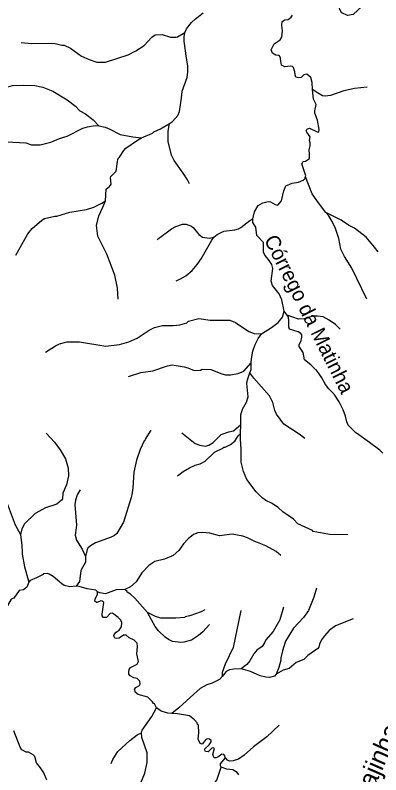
# Model space of a CAD drawing. Extents: x 393 to 446.6, y 8175.5 to 8231.
# Drawn here: x 426.13 to 430.1, y 8184.16 to 8192.41 of the extents above; entities that cross this region are included whole.
import ezdxf
from ezdxf.enums import TextEntityAlignment as Align

# ---------------------------------------------------------------- set-up
doc = ezdxf.new("R2010")
doc.units = 0
doc.header["$LTSCALE"] = 0.064
doc.linetypes.add('LONG_DASHED', pattern=[7.5, 6, -1.5])
doc.layers.add('61', color=7, linetype='Continuous')
doc.layers.add('7', color=7, linetype='Continuous', lineweight=25)
doc.layers.add('9', color=7, linetype='LONG_DASHED', lineweight=25)

msp = doc.modelspace()

# ---------------------------------------------------------------- linework, layer by layer
at = {"layer": '7'}
for points in [[(426.4711, 8187.8712), (426.5598, 8187.7758), (426.6212, 8187.6918), (426.6793, 8187.5949), (426.71, 8187.4916), (426.7132, 8187.4076), (426.689, 8187.3107), (426.6518, 8187.2203), (426.6454, 8187.1573), (426.6373, 8187.146), (426.584, 8187.1008), (426.463, 8187.0604), (426.3515, 8186.999), (426.2336, 8186.8876), (426.2062, 8186.8327), (426.191, 8186.7726)], [(427.6051, 8187.9065), (427.5448, 8187.8081), (427.5416, 8187.7919), (427.5351, 8187.7903), (427.5125, 8187.7435), (427.4899, 8187.695), (427.4496, 8187.5788), (427.4205, 8187.4496), (427.4108, 8187.2784), (427.4011, 8187.2041), (427.3917, 8187.1728), (427.3107, 8186.9038), (427.2364, 8186.7827), (427.2106, 8186.7617), (427.1735, 8186.7423), (427.0055, 8186.6825), (426.9506, 8186.6486), (426.9232, 8186.6228), (426.9134, 8186.6067), (426.8983, 8186.5331)], [(425.9034, 8187.7173), (425.93, 8187.6854), (425.9817, 8187.5982), (426.0092, 8187.5077), (426.0124, 8187.4431), (426.0027, 8187.3721), (426.0027, 8187.2946), (426.0237, 8187.1654), (426.1351, 8186.8747), (426.191, 8186.7726)], [(426.8403, 8187.2571), (426.8069, 8187.2009), (426.7875, 8187.1428), (426.7811, 8187.0976), (426.7988, 8186.8715), (426.7954, 8186.8431), (426.7859, 8186.7649), (426.8004, 8186.7084), (426.8618, 8186.6115), (426.8983, 8186.5331)], [(429.0152, 8186.5434), (429.0151, 8186.5435), (428.9643, 8186.5873), (428.8545, 8186.6486), (428.7269, 8186.6971), (428.6558, 8186.7358), (428.6058, 8186.7536), (428.4879, 8186.7746), (428.3523, 8186.7568), (428.2457, 8186.7859), (428.1649, 8186.7923), (428.1165, 8186.7891), (428.0681, 8186.7713), (428.0099, 8186.7245), (427.9598, 8186.6696), (427.9082, 8186.5986), (427.8484, 8186.5436), (427.7548, 8186.5049), (427.6482, 8186.4791), (427.5836, 8186.4355), (427.5077, 8186.3548), (427.4479, 8186.2579), (427.3834, 8186.2013), (427.3237, 8186.1725)], [(426.191, 8186.7726), (426.2062, 8186.6519), (426.2087, 8186.5789), (426.2094, 8186.5582), (426.2352, 8186.4194), (426.2831, 8186.2549)], [(426.8983, 8186.5331), (426.8957, 8186.471), (426.8456, 8186.3806), (426.8311, 8186.2595), (426.797, 8186.2103)], [(426.797, 8186.2103), (426.7278, 8186.2013), (426.6664, 8186.2175), (426.6389, 8186.2336), (426.5453, 8186.3143), (426.5033, 8186.3418), (426.4823, 8186.3467), (426.4419, 8186.3434), (426.4355, 8186.3353), (426.3661, 8186.2998), (426.296, 8186.27), (426.2831, 8186.2549)], [(426.2831, 8186.2549), (426.2595, 8186.1997), (426.2255, 8186.1706), (426.1755, 8186.1626), (426.1206, 8186.0786), (426.0916, 8186.0673), (426.0512, 8186.0011), (425.9992, 8185.9862)], [(427.0267, 8186.1485), (427.0081, 8186.1659), (426.9151, 8186.182), (426.8279, 8186.2062), (426.797, 8186.2103)], [(427.6663, 8184.8892), (427.6454, 8184.9299), (427.6337, 8184.9354), (427.624, 8184.9547), (427.5739, 8185.0048), (427.4674, 8185.0339), (427.4383, 8185.0532), (427.4302, 8185.092), (427.4415, 8185.1097), (427.4835, 8185.1323), (427.4883, 8185.1469), (427.4851, 8185.176), (427.456, 8185.2066), (427.4221, 8185.2131), (427.3801, 8185.2341), (427.3672, 8185.2535), (427.3672, 8185.2793), (427.3721, 8185.3051), (427.385, 8185.3261), (427.456, 8185.3616), (427.4706, 8185.3923), (427.4544, 8185.4763), (427.4625, 8185.5538), (427.4577, 8185.5893), (427.4253, 8185.6248), (427.372, 8185.6474), (427.3397, 8185.6782), (427.3075, 8185.6781), (427.2607, 8185.6442), (427.2348, 8185.641), (427.2203, 8185.6442), (427.2106, 8185.6539), (427.2025, 8185.6733), (427.209, 8185.683), (427.2283, 8185.7104), (427.2607, 8185.7314), (427.2865, 8185.7669), (427.2897, 8185.8154), (427.2784, 8185.8396), (427.251, 8185.8687), (427.1912, 8185.9155), (427.1654, 8185.9139), (427.1234, 8185.8687), (427.0879, 8185.8703), (427.078, 8185.8859), (427.0763, 8185.9071), (427.0959, 8186.0318), (427.0766, 8186.0479), (427.062, 8186.0496), (427.0249, 8186.0334), (427.0152, 8186.0334), (426.9991, 8186.0463), (427.0023, 8186.0673), (427.0279, 8186.1217), (427.0267, 8186.1485)], [(427.3237, 8186.1725), (427.2284, 8186.169), (427.1153, 8186.127), (427.0507, 8186.1367), (427.0267, 8186.1485)], [(427.57, 8185.9221), (427.4334, 8186.0802), (427.3833, 8186.1238), (427.3478, 8186.1464), (427.3478, 8186.1529), (427.3237, 8186.1725)], [(429.4042, 8186.1887), (429.376, 8186.0899), (429.3163, 8185.9446), (429.263, 8185.8687), (429.1548, 8185.7541), (429.0676, 8185.612), (429.0353, 8185.5086), (429.0159, 8185.4311), (429.0159, 8185.4053), (428.9933, 8185.3245), (428.9667, 8185.2523)], [(429.0458, 8185.9809), (429.0046, 8185.8445), (428.9336, 8185.7185), (428.8528, 8185.6281), (428.8399, 8185.5926), (428.8124, 8185.5554), (428.7576, 8185.5134), (428.7236, 8185.4731), (428.68, 8185.3972), (428.6477, 8185.36), (428.587, 8185.3104)], [(428.1917, 8185.9529), (428.152, 8185.9301), (428.0293, 8185.8864), (427.9776, 8185.8752), (427.9744, 8185.8703), (427.8775, 8185.8606), (427.7128, 8185.8622), (427.6547, 8185.8816), (427.57, 8185.9221)], [(428.2414, 8185.7918), (428.1698, 8185.7137), (428.123, 8185.6733), (428.0487, 8185.6232), (427.9647, 8185.6006), (427.9324, 8185.5974), (427.8404, 8185.6087), (427.7967, 8185.6291), (427.7618, 8185.6558), (427.6902, 8185.725), (427.653, 8185.7734), (427.5745, 8185.9169), (427.57, 8185.9221)], [(428.5836, 8185.9454), (428.4992, 8185.5441), (428.412, 8185.3633), (428.3797, 8185.2729), (428.3795, 8185.2348), (428.3795, 8185.2301)], [(429.8033, 8185.8544), (429.6118, 8185.7782), (429.5408, 8185.7266), (429.4891, 8185.6701), (429.4584, 8185.6265), (429.4374, 8185.5796), (429.4309, 8185.5473), (429.4196, 8185.5344), (429.3115, 8185.4569), (429.2662, 8185.4133), (429.1823, 8185.381), (429.108, 8185.3164), (429.0434, 8185.2987), (428.9667, 8185.2523)], [(428.587, 8185.3104), (428.5073, 8185.3099), (428.4588, 8185.3003), (428.4233, 8185.2825), (428.3795, 8185.2301)], [(428.9667, 8185.2523), (428.9465, 8185.2325), (428.8948, 8185.2163), (428.8544, 8185.2195), (428.7915, 8185.2373), (428.6881, 8185.2841), (428.587, 8185.3104)], [(428.3795, 8185.2301), (428.3504, 8185.1953), (428.2699, 8185.1566), (428.2134, 8185.1388), (428.1423, 8185.0968), (428.0309, 8185.0015), (427.9114, 8184.8885), (427.8343, 8184.8269)], [(427.506, 8184.6176), (427.5118, 8184.6467), (427.6175, 8184.7949), (427.6663, 8184.8892)], [(427.8343, 8184.8269), (427.7887, 8184.8304), (427.7193, 8184.8514), (427.6663, 8184.8892)], [(428.4115, 8184.348), (428.4107, 8184.3654), (428.3991, 8184.3814), (428.3765, 8184.3831), (428.3345, 8184.3524), (428.3136, 8184.3433), (428.2925, 8184.3459), (428.2844, 8184.3605), (428.2805, 8184.3804), (428.2957, 8184.4444), (428.283, 8184.4521), (428.2683, 8184.4493), (428.2279, 8184.4105), (428.2005, 8184.4122), (428.1915, 8184.4264), (428.1908, 8184.4428), (428.2392, 8184.4848), (428.2618, 8184.5204), (428.2602, 8184.5316), (428.244, 8184.5478), (428.2214, 8184.5526), (428.2037, 8184.5445), (428.1617, 8184.4945), (428.1423, 8184.4994), (428.1197, 8184.5462), (428.1262, 8184.6172), (428.123, 8184.7012), (428.1133, 8184.7076), (428.1084, 8184.7238), (428.081, 8184.7593), (428.026, 8184.8029), (427.8937, 8184.8223), (427.8343, 8184.8269)], [(426.4774, 8184.1037), (426.4451, 8184.1813), (426.4096, 8184.2362), (426.3644, 8184.2894), (426.3466, 8184.3588), (426.3289, 8184.3766), (426.2789, 8184.4057), (426.253, 8184.4073), (426.2046, 8184.4299), (426.1868, 8184.459), (426.119, 8184.6366)], [(428.9991, 8184.6987), (428.8641, 8184.572), (428.7204, 8184.4638), (428.6203, 8184.375), (428.5557, 8184.3314), (428.4976, 8184.312), (428.4604, 8184.3088), (428.4378, 8184.3185), (428.4123, 8184.3471), (428.4115, 8184.348)], [(427.177, 8184.2827), (427.1928, 8184.3265), (427.2461, 8184.4138), (427.3769, 8184.5348), (427.4577, 8184.5946), (427.506, 8184.6176)], [(427.4826, 8184.0466), (427.5145, 8184.1177), (427.5416, 8184.178), (427.5642, 8184.2943), (427.5642, 8184.3976), (427.5093, 8184.5656), (427.506, 8184.6176)], [(428.3699, 8184.2432), (428.3617, 8184.2584), (428.3617, 8184.2805), (428.4118, 8184.341), (428.4115, 8184.348)], [(427.8211, 8183.7769), (427.829, 8183.8292), (427.8452, 8183.8648), (427.8597, 8183.8857), (427.9033, 8183.9148), (427.9198, 8183.923), (427.926, 8183.9261), (428.0455, 8183.9455), (428.1391, 8183.9745), (428.1585, 8183.9858), (428.215, 8183.9987), (428.2473, 8184.0246), (428.2554, 8184.0246), (428.3216, 8184.1021), (428.3699, 8184.2432)], [(428.5594, 8184.1583), (428.542, 8184.1851), (428.496, 8184.2135), (428.4298, 8184.2232), (428.3699, 8184.2432)]]:
    msp.add_lwpolyline(points, dxfattribs=at)
at = {"layer": '9'}
for p, q in [((429.0857, 8189.1526), (429.0536, 8189.1987)), ((428.5793, 8187.8689), (428.5812, 8187.9667))]:
    msp.add_line(p, q, dxfattribs=at)
for points in [[(429.9468, 8192.5417), (429.9012, 8192.5125), (429.8023, 8192.4215), (429.7394, 8192.4102), (429.6796, 8192.4393), (429.6667, 8192.4538), (429.6554, 8192.4781), (429.6198, 8192.6234), (429.5778, 8192.6848), (429.5229, 8192.7493), (429.347, 8192.8591), (429.2947, 8192.9408), (429.2714, 8192.956), (429.2025, 8192.9747), (429.1581, 8192.9968)], [(427.9736, 8192.2271), (427.9911, 8192.2668), (428.0487, 8192.3343), (428.089, 8192.3747), (428.173, 8192.4409)], [(429.3621, 8191.6072), (429.3554, 8191.6833), (429.3426, 8191.737), (429.2985, 8191.774), (429.2678, 8191.7659), (429.2383, 8191.7373), (429.2091, 8191.7327), (429.1811, 8191.7408), (429.1706, 8191.7642), (429.1693, 8191.7982), (429.1532, 8191.8467), (429.1421, 8191.8566), (429.1176, 8191.8601), (429.0604, 8191.8543), (429.0224, 8191.8709), (429.0176, 8191.9145), (429.0145, 8191.9431), (429.0099, 8191.9613), (428.9998, 8191.9742), (428.9627, 8191.979), (428.9255, 8192.0017), (428.9126, 8192.0372), (428.9432, 8192.1034), (429.0078, 8192.147), (429.0288, 8192.1761), (429.0353, 8192.2423), (429.0272, 8192.3004), (429.0323, 8192.346), (429.0591, 8192.3624), (429.0953, 8192.367), (429.1303, 8192.3927), (429.1431, 8192.4137)], [(426.1999, 8192.1166), (426.3114, 8192.1055), (426.5275, 8192.1099), (426.5679, 8192.1067), (426.6406, 8192.0873), (426.6664, 8192.0873), (426.7326, 8192.055), (426.8537, 8191.9678), (426.9361, 8191.9306), (427.0184, 8191.9048), (427.1121, 8191.9015), (427.3608, 8191.9823), (427.4448, 8192.0259), (427.5335, 8192.0841), (427.6175, 8192.1745), (427.6546, 8192.2019), (427.729, 8192.2051), (427.821, 8192.1761), (427.8807, 8192.1761), (427.8969, 8192.1793), (427.9736, 8192.2271)], [(427.8094, 8191.2371), (427.8425, 8191.2603), (427.8985, 8191.3245), (427.9166, 8191.3671), (427.9404, 8191.5124), (427.9469, 8191.5899), (427.9986, 8191.7353), (428.0067, 8191.7998), (428.0083, 8191.8644), (427.9921, 8191.9452), (427.9679, 8192.1325), (427.9663, 8192.1777), (427.9736, 8192.2271)], [(425.8437, 8191.5644), (425.9495, 8191.606), (426.1045, 8191.648), (426.2272, 8191.6545), (426.3467, 8191.6513), (426.4339, 8191.6303), (426.5421, 8191.5867), (426.6971, 8191.4946), (426.7875, 8191.4252), (426.836, 8191.3751), (426.8957, 8191.3412), (426.9813, 8191.2767), (427.0426, 8191.2114)], [(429.284, 8190.6609), (429.2863, 8190.6693), (429.2452, 8190.8003), (429.2581, 8190.8229), (429.2582, 8190.8229), (429.2856, 8190.8293), (429.3292, 8190.8584), (429.3263, 8190.9027), (429.3241, 8190.95), (429.3352, 8190.9929), (429.3333, 8191.0281), (429.3263, 8191.0526), (429.3362, 8191.0905), (429.3001, 8191.1426), (429.292, 8191.1569), (429.2936, 8191.1684), (429.3047, 8191.1781), (429.3292, 8191.1846), (429.4099, 8191.1458), (429.4245, 8191.1442), (429.4309, 8191.1458), (429.4341, 8191.1733), (429.4164, 8191.2734), (429.3873, 8191.3509), (429.3841, 8191.3751), (429.4018, 8191.4446), (429.3712, 8191.5027), (429.3621, 8191.6072)], [(429.9543, 8191.6306), (429.8169, 8191.6174), (429.701, 8191.5913), (429.5569, 8191.5398), (429.4988, 8191.5334), (429.4681, 8191.5383), (429.4132, 8191.5689), (429.3621, 8191.6072)], [(427.503, 8191.0809), (427.6256, 8191.133), (427.6401, 8191.1458), (427.7112, 8191.1781), (427.8075, 8191.2358), (427.8094, 8191.2371)], [(428.0244, 8190.581), (428.0046, 8190.6242), (427.9582, 8190.6969), (427.8581, 8190.8342), (427.8306, 8190.8923), (427.7951, 8191.0409), (427.7951, 8191.1539), (427.8094, 8191.2371)], [(425.6977, 8190.9926), (425.8219, 8191.0183), (426.0383, 8191.0377), (426.2482, 8191.028), (426.3112, 8191.0037), (426.4048, 8191.0037), (426.5211, 8191.0328), (426.6131, 8191.0732), (426.6987, 8191.1006), (426.8667, 8191.1846), (426.9183, 8191.2007), (427.0023, 8191.2136), (427.0426, 8191.2114)], [(427.0426, 8191.2114), (427.1092, 8191.1963), (427.1621, 8191.1765), (427.2736, 8191.1167), (427.4092, 8191.0909), (427.503, 8191.0809)], [(427.1123, 8190.3981), (427.1217, 8190.5217), (427.1557, 8190.5516), (427.1751, 8190.5774), (427.167, 8190.6469), (427.1734, 8190.6614), (427.23, 8190.7195), (427.2428, 8190.8253), (427.2461, 8190.8455), (427.2558, 8190.8649), (427.2655, 8190.8697), (427.3128, 8190.9449), (427.3349, 8190.9682), (427.4593, 8191.0554), (427.503, 8191.0809)], [(428.714, 8190.1996), (428.7301, 8190.2787), (428.7721, 8190.3449), (428.8206, 8190.3756), (428.8787, 8190.3885), (428.9029, 8190.3853), (428.9562, 8190.3562), (428.9853, 8190.3481), (429.0224, 8190.3966), (429.0482, 8190.5048), (429.0708, 8190.5613), (429.1387, 8190.5871), (429.2097, 8190.5984), (429.2581, 8190.6194), (429.2775, 8190.6372), (429.284, 8190.6609)], [(429.5065, 8190.2712), (429.4244, 8190.3764), (429.3582, 8190.4741), (429.285, 8190.6584), (429.284, 8190.6609)], [(426.1394, 8189.805), (426.2724, 8190.0365), (426.3192, 8190.0962), (426.421, 8190.1882), (426.4533, 8190.206), (426.5631, 8190.2318), (426.5873, 8190.2318), (426.7278, 8190.2738), (426.9086, 8190.3013), (426.9877, 8190.3272), (427.0733, 8190.3707), (427.1123, 8190.3981)], [(427.2504, 8189.3271), (427.2445, 8189.4471), (427.2154, 8189.5892), (427.1299, 8189.8185), (427.0297, 8190.0139), (427.0168, 8190.1269), (427.041, 8190.2335), (427.0862, 8190.3272), (427.1123, 8190.3981)], [(429.9494, 8189.3272), (429.7862, 8189.6651), (429.707, 8189.791), (429.6683, 8189.8702), (429.6473, 8189.988), (429.6085, 8190.0946), (429.573, 8190.1705), (429.5359, 8190.2335), (429.5065, 8190.2712)], [(430.072, 8189.8415), (430.0349, 8189.8944), (429.9412, 8190.001), (429.8169, 8190.1011), (429.7523, 8190.1334), (429.6731, 8190.185), (429.5065, 8190.2712)], [(428.2905, 8190.0011), (428.3267, 8190.0326), (428.3991, 8190.0656), (428.517, 8190.08), (428.5557, 8190.093), (428.5832, 8190.1075), (428.6793, 8190.1831), (428.714, 8190.1996)], [(429.0536, 8189.1987), (429.0289, 8189.32), (428.9998, 8189.3857), (428.9271, 8189.4778), (428.911, 8189.5246), (428.9303, 8189.6602), (428.9174, 8189.7054), (428.8835, 8189.7587), (428.8415, 8189.8055), (428.8302, 8189.8395), (428.8302, 8189.9428), (428.7576, 8190.0187), (428.7462, 8190.1108), (428.7139, 8190.1624), (428.714, 8190.1996)], [(427.6748, 8189.9778), (427.8307, 8190.093), (427.8759, 8190.1172), (427.9486, 8190.1447), (427.9906, 8190.1447), (428.0455, 8190.1204), (428.0648, 8190.1059), (428.1262, 8190.0316), (428.1681, 8190.0009), (428.2441, 8189.9928), (428.2905, 8190.0011)], [(427.8798, 8189.5278), (427.9292, 8189.5488), (427.9841, 8189.5827), (428.0535, 8189.6409), (428.11, 8189.7054), (428.152, 8189.7668), (428.2666, 8189.9702), (428.2905, 8190.0011)], [(428.8071, 8188.9512), (428.9144, 8189.02), (428.9869, 8189.0757), (429.0353, 8189.1338), (429.0536, 8189.1987)], [(426.4621, 8188.7522), (426.5711, 8188.8221), (426.6163, 8188.8415), (426.6987, 8188.8641), (426.8311, 8188.8641), (427.1169, 8188.8189), (427.2671, 8188.8367), (427.3688, 8188.8657), (427.456, 8188.9045), (427.5868, 8188.9917), (427.6466, 8189.0208), (427.7322, 8189.0434), (427.8468, 8189.0418), (427.9211, 8189.0482), (427.997, 8189.0724), (428.0164, 8189.0886), (428.1262, 8189.1176), (428.2489, 8189.0983), (428.462, 8189.1015), (428.5234, 8189.074), (428.6704, 8188.9756), (428.7285, 8188.9562), (428.8071, 8188.9512)], [(429.6611, 8189.0008), (429.6086, 8189.0531), (429.5408, 8189.1015), (429.4745, 8189.137), (429.4148, 8189.1451), (429.376, 8189.1435), (429.3227, 8189.1322), (429.2695, 8189.1128), (429.2081, 8189.1096), (429.0857, 8189.1526)], [(430.1236, 8187.6563), (430.0898, 8187.687), (429.9799, 8187.7725), (429.8378, 8187.871), (429.8315, 8187.8771), (429.7474, 8187.9582), (429.7329, 8187.9954), (429.72, 8188.0584), (429.6941, 8188.1246), (429.6489, 8188.2134), (429.5956, 8188.2957), (429.5391, 8188.3522), (429.5003, 8188.4007), (429.46, 8188.475), (429.4327, 8188.5159), (429.4019, 8188.5622), (429.3922, 8188.5638), (429.3421, 8188.6138), (429.2743, 8188.6687), (429.2581, 8188.7495), (429.2145, 8188.8141), (429.2145, 8188.8319), (429.2371, 8188.8803), (429.2436, 8188.9142), (429.2431, 8188.9392), (429.2352, 8188.9565), (429.2049, 8188.9723), (429.1107, 8189.0027), (429.1026, 8189.0249), (429.1049, 8189.0914), (429.0991, 8189.1334), (429.0857, 8189.1526)], [(428.6965, 8188.6405), (428.698, 8188.68), (428.7131, 8188.764), (428.7376, 8188.8363), (428.7697, 8188.9022), (428.8071, 8188.9512)], [(427.3648, 8188.4888), (427.4964, 8188.5299), (427.6288, 8188.5493), (427.7871, 8188.6025), (427.8371, 8188.6138), (427.9679, 8188.5944), (428.0083, 8188.5832), (428.0745, 8188.5525), (428.1456, 8188.5557), (428.1633, 8188.5686), (428.2554, 8188.5654), (428.3781, 8188.5153), (428.4169, 8188.5072), (428.4701, 8188.5057), (428.5525, 8188.5202), (428.6155, 8188.546), (428.6944, 8188.638), (428.6965, 8188.6405)], [(428.6813, 8188.5282), (428.6937, 8188.565), (428.6965, 8188.6405)], [(428.5812, 8187.9667), (428.5831, 8188.0697), (428.6009, 8188.1326), (428.6445, 8188.2101), (428.6606, 8188.2667), (428.6477, 8188.412), (428.6558, 8188.4524), (428.6813, 8188.5282)], [(429.2764, 8187.813), (429.2162, 8187.863), (429.0482, 8187.9712), (428.9707, 8188.0777), (428.9513, 8188.1197), (428.9287, 8188.2053), (428.8924, 8188.2795), (428.8916, 8188.2812), (428.722, 8188.4685), (428.6813, 8188.5282)], [(427.9411, 8187.8759), (428.0874, 8187.7612), (428.1391, 8187.7402), (428.1956, 8187.7306), (428.2347, 8187.7417), (428.2812, 8187.7709), (428.37, 8187.8565), (428.454, 8187.8872), (428.5041, 8187.8985), (428.5812, 8187.9667)], [(427.8951, 8187.4077), (427.9582, 8187.4567), (428.0244, 8187.4964), (428.0874, 8187.5238), (428.1423, 8187.54), (428.194, 8187.5691), (428.2957, 8187.6643), (428.3942, 8187.7128), (428.3958, 8187.7192), (428.412, 8187.7208), (428.4701, 8187.7483), (428.5169, 8187.7838), (428.5541, 8187.842), (428.5793, 8187.8689)], [(429.7431, 8186.7675), (429.544, 8186.7714), (429.368, 8186.8037), (429.3599, 8186.815), (429.2, 8186.8876), (429.1548, 8186.9377), (429.0401, 8187.0168), (428.9869, 8187.0636), (428.9142, 8187.1105), (428.8528, 8187.1411), (428.8141, 8187.1702), (428.7495, 8187.2364), (428.6477, 8187.3705), (428.6106, 8187.4544), (428.5864, 8187.5562), (428.5864, 8187.7047), (428.5835, 8187.7445), (428.5783, 8187.8145), (428.5793, 8187.8689)]]:
    msp.add_lwpolyline(points, dxfattribs=at)

# ---------------------------------------------------------------- texts
at = {"layer": '61'}
for s, height, rotation, p in [('Córrego da Matinha', 0.16, 296.565, (429.2536, 8189.1311)), ('Córrego da Lajinha', 0.2, 66.318, (429.8591, 8183.6171))]:
    msp.add_text(s, height=height, rotation=rotation, dxfattribs=at).set_placement(p, align=Align.CENTER)

doc.saveas('drawing.dxf')
